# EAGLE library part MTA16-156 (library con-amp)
AMP connector
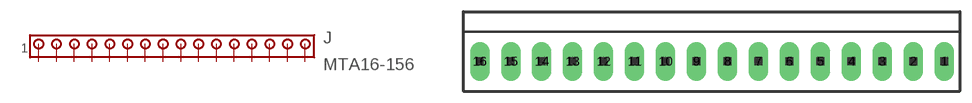
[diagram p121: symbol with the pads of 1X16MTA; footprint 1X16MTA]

Designator prefix J

## MTA16-156 (OC_FARNELL: unknown; OC_NEWARK: unknown)  [1X16MTA]
1  1  pas
2  2  pas
3  3  pas
4  4  pas
5  5  pas
6  6  pas
7  7  pas
8  8  pas
9  9  pas
10  10  pas
11  11  pas
12  12  pas
13  13  pas
14  14  pas
15  15  pas
16  16  pas

## Footprint 1X16MTA (pad centres in mm)
AMP MTA connector
drill 1.676 long: 1 29.718,0; 2 25.756,0; 3 21.793,0; 4 17.831,0; 5 13.868,0; 6 9.906,0; 7 5.944,0; 8 1.981,0; 9 -1.981,0; 10 -5.944,0; 11 -9.906,0; 12 -13.868,0; 13 -17.831,0; 14 -21.793,0; 15 -25.756,0; 16 -29.718,0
